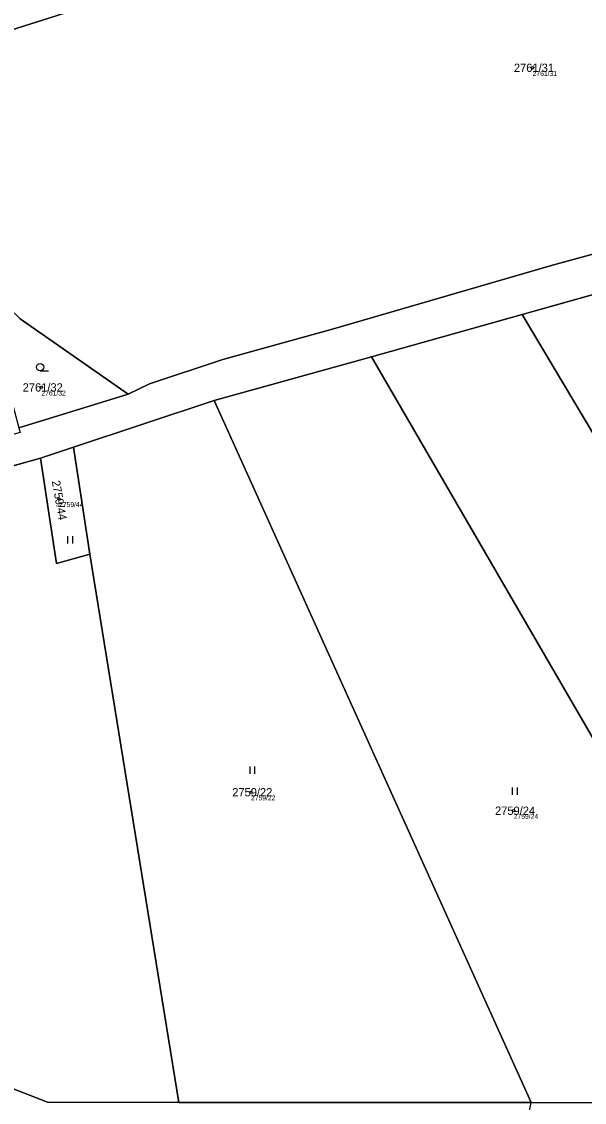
# Model space of a CAD drawing. Extents: x -761891 to -756141, y -1178507 to -1171885.
# Drawn here: x -757272.4 to -757157.1, y -1176752.8 to -1176531.1 of the extents above; entities that cross this region are included whole.
import ezdxf

# ---------------------------------------------------------------- set-up
doc = ezdxf.new("R2010")
doc.units = 0
for name, color, linetype in [('Definiční body', 7, 'Continuous'), ('Hranice parcel', 7, 'Continuous'), ('Parcelní čísla', 7, 'Continuous'), ('Polygon parcely', 7, 'Continuous'), ('Značky kultur', 7, 'Continuous')]:
    doc.layers.add(name, color=color, linetype=linetype)

msp = doc.modelspace()

# ---------------------------------------------------------------- linework, layer by layer
at = {"layer": 'Definiční body'}
for centre in [(-757167.67, -1176540.6), (-757268.34, -1176606.14), (-757264.72, -1176629), (-757225.39, -1176689.15), (-757171.54, -1176692.94)]:
    msp.add_circle(centre, 0.25, dxfattribs=at)
at = {"layer": 'Hranice parcel'}
for p, q in [((-757169.8, -1176591.17), (-757137.03, -1176581.99)), ((-757200.7, -1176599.85), (-757169.8, -1176591.17)), ((-757232.97, -1176608.85), (-757200.7, -1176599.85)), ((-757250.53, -1176607.54), (-757272.99, -1176614.4)), ((-757261.75, -1176618.42), (-757232.97, -1176608.85)), ((-757167.95, -1176752.76), (-757232.97, -1176608.85)), ((-757268.55, -1176620.66), (-757261.75, -1176618.42)), ((-757261.75, -1176618.42), (-757258.42, -1176640.35)), ((-757294.28, -1176627.84), (-757268.55, -1176620.66)), ((-757258.42, -1176640.35), (-757240.19, -1176752.74)), ((-757240.19, -1176752.74), (-757167.95, -1176752.76))]:
    msp.add_line(p, q, dxfattribs=at)
for points in [[(-757061.14, -1176465.09), (-757209.5, -1176512.17), (-757358.27, -1176559.38)], [(-756996.69, -1176536.46), (-757027.22, -1176543.82), (-757076.85, -1176557.43), (-757163.63, -1176581.04), (-757208.51, -1176594.14), (-757231.16, -1176600.4), (-757246.21, -1176605.4), (-757250.53, -1176607.54)], [(-757250.53, -1176607.54), (-757272.67, -1176592.07), (-757274.94, -1176589.9), (-757275.6, -1176589.46), (-757281.32, -1176588.07), (-757283.41, -1176588.74)], [(-757043.58, -1176803.15), (-757106.69, -1176697.16), (-757169.8, -1176591.17)], [(-757098.26, -1176776.29), (-757149.51, -1176688.02), (-757200.7, -1176599.85)], [(-757258.42, -1176640.35), (-757265.27, -1176642.23), (-757268.55, -1176620.66)], [(-757331.72, -1176746.18), (-757311.35, -1176746.69), (-757295.32, -1176741.73), (-757267.12, -1176752.73), (-757240.19, -1176752.74)]]:
    msp.add_lwpolyline(points, dxfattribs=at)
at = {"layer": 'Polygon parcely'}
for points in [[(-757081.51, -1176442.42), (-757096.71, -1176425.49), (-757254.69, -1176475.68), (-757412.45, -1176525.8), (-757362.32, -1176560.67), (-757358.27, -1176559.38), (-757209.5, -1176512.17), (-757061.14, -1176465.09)], [(-757038.55, -1176490.24), (-757059.3, -1176467.14), (-757061.14, -1176465.09), (-757209.5, -1176512.17), (-757358.27, -1176559.38), (-757300.37, -1176591.81), (-757298.63, -1176593.59), (-757283.41, -1176588.74), (-757281.32, -1176588.07), (-757275.6, -1176589.46), (-757274.94, -1176589.9), (-757272.67, -1176592.07), (-757250.53, -1176607.54), (-757246.21, -1176605.4), (-757231.16, -1176600.4), (-757208.51, -1176594.14), (-757163.63, -1176581.04), (-757076.85, -1176557.43), (-757027.22, -1176543.82), (-756996.69, -1176536.46), (-757021.75, -1176508.95)], [(-757008.08, -1176804.06), (-757072.61, -1176692.93), (-757137.03, -1176581.99), (-757169.8, -1176591.17), (-757106.69, -1176697.16), (-757043.58, -1176803.15)], [(-757275.6, -1176589.46), (-757281.32, -1176588.07), (-757283.41, -1176588.74), (-757278.55, -1176593.5), (-757272.99, -1176614.4), (-757250.53, -1176607.54), (-757272.67, -1176592.07), (-757274.94, -1176589.9)], [(-757106.69, -1176697.16), (-757169.8, -1176591.17), (-757200.7, -1176599.85), (-757149.51, -1176688.02), (-757098.26, -1176776.29), (-757044.92, -1176803.12), (-757043.58, -1176803.15)], [(-757149.51, -1176688.02), (-757200.7, -1176599.85), (-757232.97, -1176608.85), (-757167.95, -1176752.76), (-757145, -1176752.77), (-757098.26, -1176776.29)], [(-757261.75, -1176618.42), (-757258.42, -1176640.35), (-757240.19, -1176752.74), (-757167.95, -1176752.76), (-757232.97, -1176608.85)], [(-757261.75, -1176618.42), (-757268.55, -1176620.66), (-757265.27, -1176642.23), (-757258.42, -1176640.35)], [(-757295.32, -1176741.73), (-757267.12, -1176752.73), (-757240.19, -1176752.74), (-757258.42, -1176640.35), (-757265.27, -1176642.23), (-757268.55, -1176620.66), (-757294.28, -1176627.84), (-757292.93, -1176639.68), (-757297.76, -1176640.97), (-757313.58, -1176683.6), (-757331.72, -1176746.18), (-757311.35, -1176746.69)], [(-757340.54, -1176789.77), (-757306.99, -1176776.83), (-757299.78, -1176764.89), (-757273.72, -1176761.82), (-757231.59, -1176771.39), (-757193.65, -1176778.62), (-757184.72, -1176788.57), (-757180.65, -1176799.87), (-757177.69, -1176800.51), (-757167.95, -1176752.76), (-757240.19, -1176752.74), (-757267.12, -1176752.73), (-757295.32, -1176741.73), (-757311.35, -1176746.69), (-757331.72, -1176746.18), (-757358.99, -1176745.49), (-757357.34, -1176794.2)]]:
    msp.add_lwpolyline(points, close=True, dxfattribs=at)
msp.add_lwpolyline([(-757076.85, -1176557.43), (-757163.63, -1176581.04), (-757208.51, -1176594.14), (-757231.16, -1176600.4), (-757246.21, -1176605.4), (-757250.53, -1176607.54), (-757272.99, -1176614.4), (-757272.73, -1176615.37), (-757289.31, -1176619.96), (-757292.65, -1176619.15), (-757294.76, -1176622.57), (-757294.28, -1176627.84), (-757268.55, -1176620.66), (-757261.75, -1176618.42), (-757232.97, -1176608.85), (-757200.7, -1176599.85), (-757169.8, -1176591.17), (-757137.03, -1176581.99)], dxfattribs=at)
at = {"layer": 'Značky kultur'}
for p, q in [((-757268.62, -1176602.74), (-757266.87, -1176602.74)), ((-757262.9, -1176638.13), (-757262.9, -1176636.63)), ((-757261.9, -1176638.13), (-757261.9, -1176636.63)), ((-757225.58, -1176685.4), (-757225.58, -1176683.9)), ((-757224.58, -1176685.4), (-757224.58, -1176683.9)), ((-757171.8, -1176689.7), (-757171.8, -1176688.2)), ((-757170.8, -1176689.7), (-757170.8, -1176688.2))]:
    msp.add_line(p, q, dxfattribs=at)
msp.add_circle((-757268.62, -1176601.99), 0.75, dxfattribs=at)

# ---------------------------------------------------------------- texts
at = {"layer": 'Definiční body'}
for s, p in [('2761/31', (-757167.67, -1176542.26)), ('2761/32', (-757268.34, -1176607.8)), ('2759/44', (-757264.72, -1176630.66)), ('2759/22', (-757225.39, -1176690.81)), ('2759/24', (-757171.54, -1176694.6))]:
    msp.add_text(s, height=1, dxfattribs=at).set_placement(p)
at = {"layer": 'Parcelní čísla'}
for s, p in [('2761/31', (-757171.51, -1176541.45)), ('2761/32', (-757272.18, -1176606.99)), ('2759/22', (-757229.23, -1176690)), ('2759/24', (-757175.38, -1176693.79))]:
    msp.add_text(s, height=1.7, dxfattribs=at).set_placement(p)
msp.add_text('2759/44', height=1.7, rotation=280, dxfattribs=at).set_placement((-757266.22, -1176625.37))

doc.saveas('drawing.dxf')
